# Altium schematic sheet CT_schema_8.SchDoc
size 308 x 195 mm
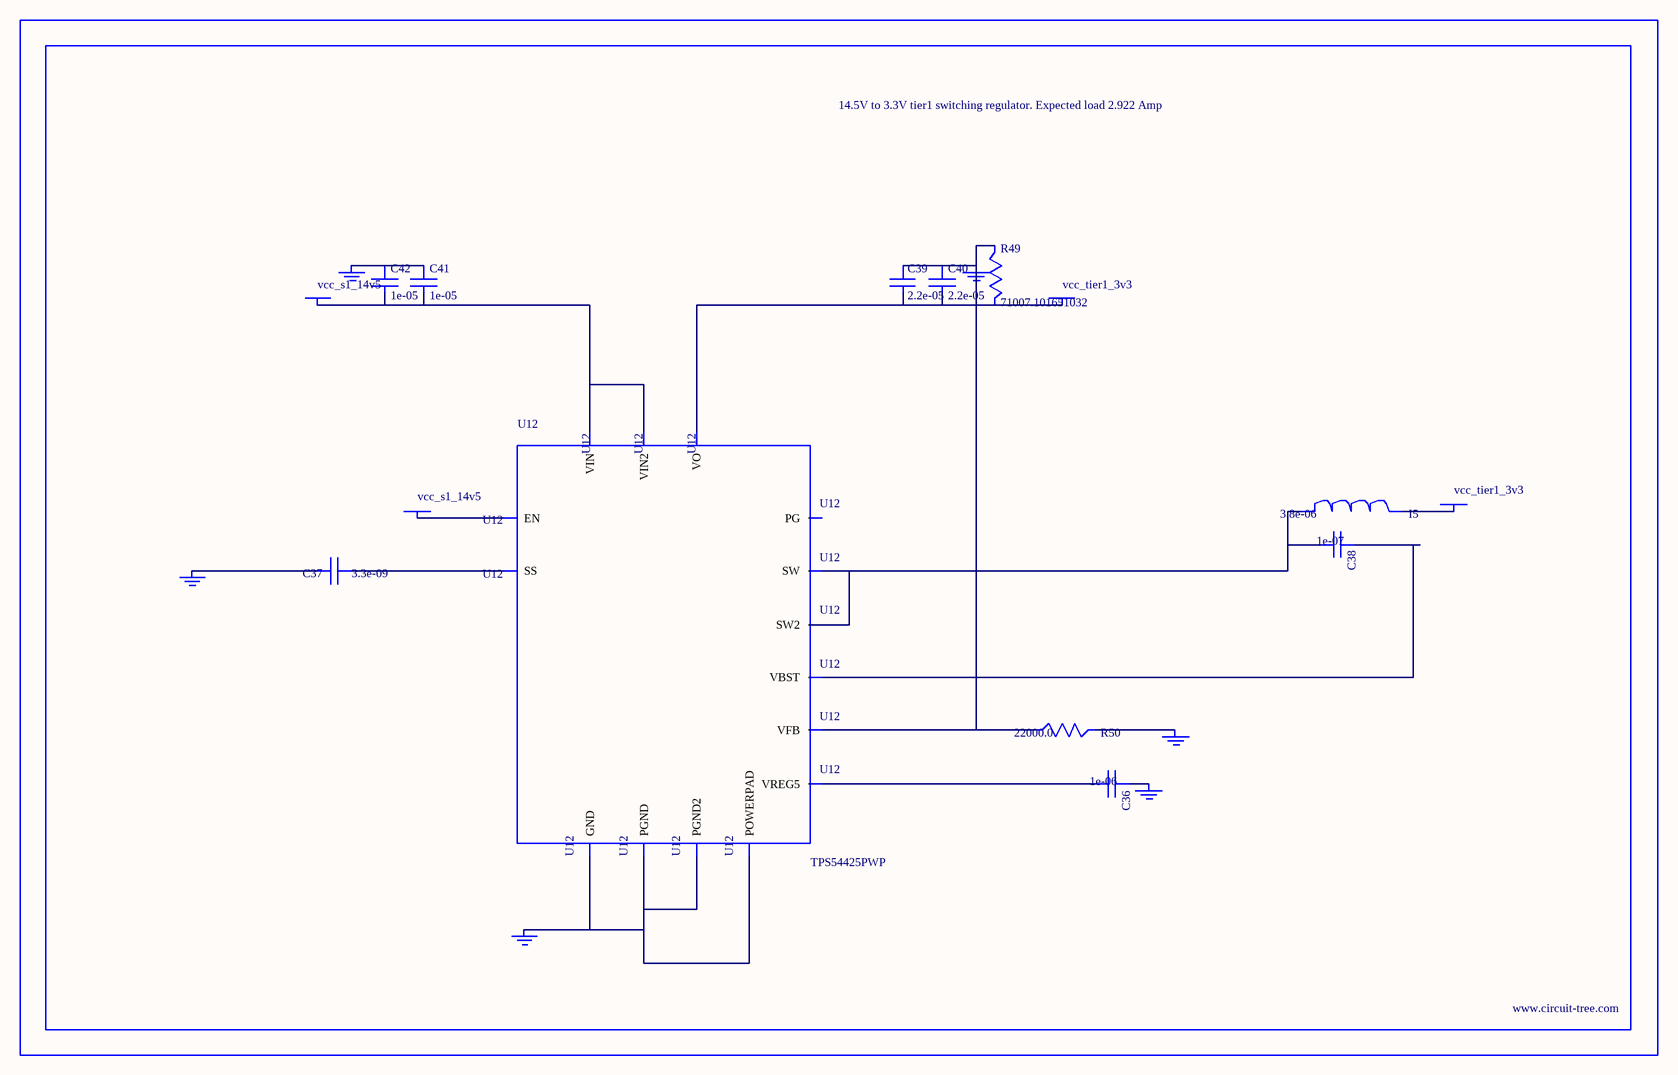
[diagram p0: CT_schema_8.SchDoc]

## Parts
BORDER7  (no value)
C36  1e-06  [C0603]
C37  3.3e-09  [C0402]
C38  1e-07  [C0402]
C39  2.2e-05  [C1210]
C40  2.2e-05  [C1210]
C41  1e-05  [C1206]
C42  1e-05  [C1206]
GND_INSTANCE_7_0  (no value)
GND_INSTANCE_7_1  (no value)
GND_INSTANCE_7_2  (no value)
GND_INSTANCE_7_3  (no value)
GND_INSTANCE_7_4  (no value)
GND_INSTANCE_7_5  (no value)
I5  3.8e-06  [DR1040]
POWER_INSTANCE_7_0  vcc_tier1_3v3
POWER_INSTANCE_7_1  vcc_s1_14v5
POWER_INSTANCE_7_2  vcc_tier1_3v3
POWER_INSTANCE_7_3  vcc_s1_14v5
R49  71007.101651032  [R0603]
R50  22000.0  [R0603]
U12  TPS54425PWP  [HTSSOP14]

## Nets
NetC36_1: C36.1 GND_INSTANCE_7_2.0(GND)
NetC36_2: C36.2 U12.3(VREG5)
NetC37_1: C37.1 U12.4(SS)
NetC37_2: C37.2 GND_INSTANCE_7_3.0(GND)
NetC38_1: C38.1 U12.12(VBST)
NetC38_2: C38.2 I5.1 U12.10(SW) U12.11(SW2)
NetC39_1: C39.1 C40.1 GND_INSTANCE_7_0.0(GND) R49.1 R50.1 U12.2(VFB)
NetC39_2: C39.2 C40.2 POWER_INSTANCE_7_0.0(PWR) R49.2 U12.1(VO)
NetC41_1: C41.1 C42.1 GND_INSTANCE_7_5.0(GND)
NetC41_2: C41.2 C42.2 POWER_INSTANCE_7_3.0(PWR) U12.13(VIN) U12.14(VIN2)
NetGND_INSTANCE_7_1_0: GND_INSTANCE_7_1.0(GND) R50.2
NetGND_INSTANCE_7_4_0: GND_INSTANCE_7_4.0(GND) U12.5(GND) U12.8(PGND) U12.9(PGND2) U12.15(POWERPAD)
NetI5_2: I5.2 POWER_INSTANCE_7_2.0(PWR)
NetPOWER_INSTANCE_7_1_0: POWER_INSTANCE_7_1.0(PWR) U12.7(EN)

Not connected (* = marked no-connect by the designer): U12 6(PG)

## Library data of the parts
BORDER7 = BORDER_PAGE7
C36 = C0603C105K3RACTU
C37 = C0402C332K3RAC
C38 = C0402C104K3RACTU
C39 C40 = GRM32ER61E226ME15L
C41 C42 = C1206C106K3RACTU
GND_INSTANCE_7_0-GND_INSTANCE_7_5 = GND
I5 = DR1040-3R8-R
POWER_INSTANCE_7_0-POWER_INSTANCE_7_3 = PWR
R49 = R49
R50 = RC0603JR-0722KL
